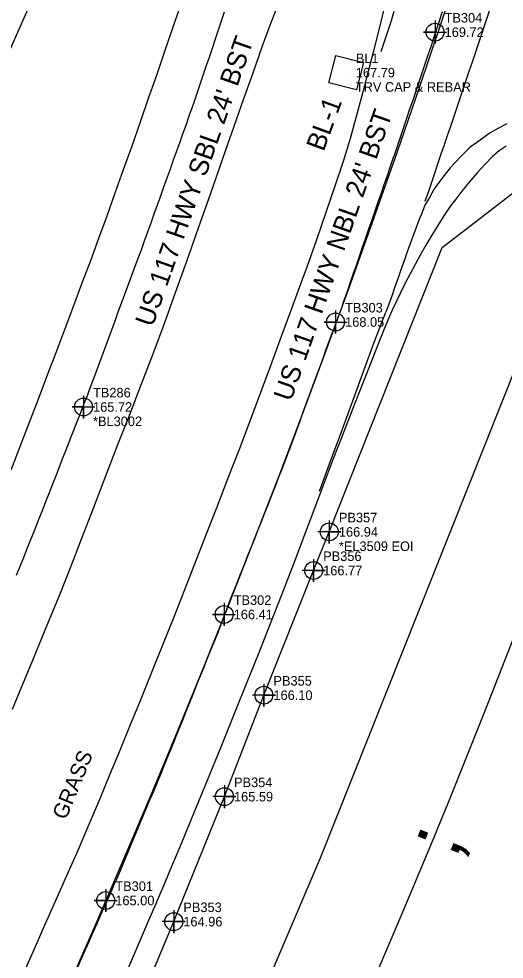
# Model space of a CAD drawing. Extents: x 2262665 to 2270527, y 505476 to 514960.
# Drawn here: x 2266059.9 to 2266186.8, y 509202.7 to 509448.8 of the extents above; entities that cross this region are included whole.
import ezdxf

# ---------------------------------------------------------------- set-up
doc = ezdxf.new("R2010")
doc.units = 0
for name, color, linetype in [('CTL Secondary Horizontal and Vertical CELL', 7, 'Continuous'), ('CTL Secondary Horizontal and Vertical Cogo Comment', 7, 'Continuous'), ('CTL Secondary Horizontal and Vertical Cogo Elevation', 7, 'Continuous'), ('CTL Secondary Horizontal and Vertical Cogo Number', 7, 'Continuous'), ('CTL Secondary Horizontal and Vertical Text', 7, 'Continuous'), ('Exist Horizontal Alignment', 7, 'Continuous'), ('Exist Other Culture Fence Line', 7, 'Continuous'), ('Exist Right of Way Control of Access CA Symbol CELL', 7, 'Continuous'), ('Exist Right of Way Control of Access Line', 7, 'Continuous'), ('Exist Roads EOP', 7, 'Continuous'), ('Exist Roads EOP Text', 7, 'Continuous'), ('Exist Roads EOT', 7, 'Continuous'), ('Exist Roads EOT Cogo Comment', 7, 'Continuous'), ('Exist Roads EOT Cogo Elevation', 7, 'Continuous'), ('Exist Roads EOT Cogo Number', 7, 'Continuous'), ('Exist Roads EOT Cogo Point CELL', 7, 'Continuous'), ('Exist Utilities Telephone UG Cable SUE LOS C', 7, 'Continuous'), ('Exist Utilities Telephone UG Cable SUE LOS C Cogo Comment', 7, 'Continuous'), ('Exist Utilities Telephone UG Cable SUE LOS C Cogo Elevation', 7, 'Continuous'), ('Exist Utilities Telephone UG Cable SUE LOS C Cogo Number', 7, 'Continuous'), ('Exist Utilities Telephone UG Cable SUE LOS C Cogo Point CELL', 7, 'Continuous'), ('Exist Utilities Water UG Line SUE LOS C', 7, 'Continuous'), ('Exist Vegetation Hedge Row Text', 7, 'Continuous')]:
    doc.layers.add(name, color=color, linetype=linetype)

msp = doc.modelspace()

# ---------------------------------------------------------------- linework, layer by layer
at = {"layer": 'CTL Secondary Horizontal and Vertical CELL'}
msp.add_line((2266145.46, 509434.72), (2266145.46, 509434.72), dxfattribs=at)
msp.add_lwpolyline([(2266140.98, 509432.05), (2266142.78, 509439.24), (2266149.99, 509437.44), (2266148.18, 509430.25)], close=True, dxfattribs=at)
at = {"layer": 'Exist Horizontal Alignment'}
msp.add_arc((2263436.25, 510359.19), 2882, 309.60499, 355.6461, dxfattribs=at)
at = {"layer": 'Exist Other Culture Fence Line'}
msp.add_lwpolyline([(2265935.11, 509632.71), (2265963.38, 509609.48), (2265980.51, 509595.58), (2265997.14, 509582.86), (2266019.57, 509564.09), (2266044.87, 509543.13), (2266056.13, 509534.43), (2266088.53, 509508.87), (2266073.89, 509477.67), (2266057.87, 509441.48), (2266042.86, 509409.08), (2266015.5, 509349.02), (2265987.41, 509287.57), (2265963.64, 509234.96), (2265936.09, 509175.26), (2265921.16, 509143.13)], dxfattribs=at)
at = {"layer": 'Exist Right of Way Control of Access CA Symbol CELL'}
msp.add_line((2266170.05, 509238.58), (2266170.05, 509238.58), dxfattribs=at)
at = {"layer": 'Exist Right of Way Control of Access Line'}
for radius, end in [(2754.56, 355.6461), (2954.56, 339.73535)]:
    msp.add_arc((2263436.25, 510359.19), radius, 309.60499, end, dxfattribs=at)
at = {"layer": 'Exist Roads EOP'}
for points in [[(2266102.21, 509452.41), (2266100.02, 509446.08), (2266097.93, 509440.01), (2266095.86, 509434.02), (2266093.75, 509427.95), (2266091.61, 509421.79), (2266089.42, 509415.54), (2266087.22, 509409.31), (2266085.04, 509403.21), (2266082.89, 509397.22), (2266080.75, 509391.36), (2266078.61, 509385.53), (2266076.42, 509379.64), (2266074.19, 509373.69), (2266071.92, 509367.67), (2266069.29, 509360.71), (2266067.76, 509356.68), (2266064.43, 509347.92), (2266061.31, 509339.79), (2266057.79, 509330.7)], [(2266127.29, 509451.55), (2266125.64, 509447.36), (2266123.55, 509441.66), (2266121.07, 509434.61), (2266118.59, 509427.6), (2266116.12, 509420.65), (2266113.25, 509412.49), (2266109.99, 509403.14), (2266106.79, 509394.01), (2266103.72, 509385.31), (2266100.79, 509377.1), (2266097.96, 509369.27), (2266095, 509361.32), (2266091.89, 509353.2), (2266088.81, 509345.2), (2266085.74, 509337.3), (2266082.58, 509329.13), (2266079.36, 509320.71), (2266076.3, 509312.78), (2266073.42, 509305.35), (2266070.41, 509297.84), (2266067.14, 509289.87), (2266065.19, 509285.15), (2266063.01, 509279.85), (2266060.59, 509273.97), (2266058.17, 509268.08)], [(2266060.79, 509198.24), (2266063.65, 509204.67), (2266066.56, 509211.27), (2266069.51, 509217.94), (2266072.48, 509224.59), (2266075.43, 509231.29), (2266078.33, 509238.09), (2266081.14, 509244.79), (2266083.81, 509251.19), (2266086.39, 509257.45), (2266088.96, 509263.71), (2266091.68, 509270.39), (2266094.71, 509277.88), (2266097.75, 509285.44), (2266100.49, 509292.3), (2266103.15, 509299.03), (2266105.95, 509306.19), (2266108.83, 509313.62), (2266111.75, 509321.14), (2266114.67, 509328.69), (2266117.56, 509336.22), (2266120.37, 509343.63), (2266123.05, 509350.83), (2266125.75, 509358.12), (2266128.59, 509365.74), (2266131.41, 509373.31), (2266134.02, 509380.45), (2266135.28, 509383.93), (2266137.79, 509391.04), (2266140.27, 509398.26), (2266142.61, 509405.13), (2266144.78, 509411.61), (2266146.71, 509417.9), (2266148.4, 509423.99), (2266149.93, 509429.7), (2266151.34, 509435.1), (2266152.81, 509440.8), (2266154.3, 509446.68), (2266155.43, 509451.4)], [(2266187.34, 509415.54), (2266185.52, 509414.28), (2266183.78, 509412.76), (2266181.82, 509410.79), (2266179.74, 509408.52), (2266177.67, 509406.07), (2266175.74, 509403.69), (2266174.12, 509401.64), (2266172.6, 509399.61), (2266171.03, 509397.27), (2266169.43, 509394.76), (2266167.85, 509392.17), (2266166.32, 509389.57), (2266164.87, 509387.01), (2266163.5, 509384.5), (2266162.18, 509382.05), (2266160.94, 509379.64), (2266159.77, 509377.29), (2266158.65, 509374.93), (2266157.54, 509372.54), (2266156.4, 509369.95), (2266155.19, 509367.03), (2266153.79, 509363.55), (2266152.09, 509359.27), (2266149.9, 509353.73), (2266147.05, 509346.45), (2266143.71, 509337.85), (2266141.94, 509333.21), (2266140.1, 509328.34), (2266138.26, 509323.49), (2266134.87, 509314.52), (2266131.79, 509306.39), (2266128.66, 509298.25), (2266125.46, 509290.07), (2266122.46, 509282.5), (2266119.62, 509275.41), (2266116.38, 509267.33), (2266112.71, 509258.25), (2266109.15, 509249.48), (2266105.7, 509241.06), (2266101.89, 509231.88), (2266099.81, 509226.94), (2266097.7, 509221.93), (2266095.62, 509217.02), (2266093.57, 509212.21), (2266091.56, 509207.5), (2266089.54, 509202.8), (2266087.46, 509198.03)]]:
    msp.add_lwpolyline(points, dxfattribs=at)
at = {"layer": 'Exist Roads EOT'}
for points in [[(2266059.31, 509303.25), (2266060.24, 509305.57), (2266061.18, 509307.89), (2266062.12, 509310.2), (2266063.06, 509312.52), (2266063.34, 509313.2), (2266064.25, 509315.53), (2266065.16, 509317.86), (2266066.07, 509320.19), (2266066.98, 509322.51), (2266067.89, 509324.84), (2266068.8, 509327.17), (2266069.72, 509329.5), (2266070.63, 509331.83), (2266071.54, 509334.15), (2266072.45, 509336.48), (2266073.36, 509338.81), (2266074.27, 509341.14), (2266075.18, 509343.46), (2266076.09, 509345.79), (2266077, 509348.12), (2266077.91, 509350.45), (2266078.13, 509351), (2266078.99, 509353.35), (2266079.86, 509355.69), (2266080.73, 509358.04), (2266081.59, 509360.38), (2266082.46, 509362.73), (2266083.32, 509365.07), (2266084.19, 509367.42), (2266085.06, 509369.76), (2266085.92, 509372.11), (2266086.79, 509374.45), (2266087.66, 509376.79), (2266088.52, 509379.14), (2266089.39, 509381.48), (2266090.26, 509383.83), (2266091.12, 509386.17), (2266091.95, 509388.41), (2266092.79, 509390.76), (2266093.64, 509393.11), (2266094.48, 509395.47), (2266095.32, 509397.82), (2266096.17, 509400.17), (2266097.01, 509402.53), (2266097.85, 509404.88), (2266098.7, 509407.23), (2266099.54, 509409.58), (2266100.38, 509411.94), (2266101.23, 509414.29), (2266102.07, 509416.64), (2266102.8, 509418.69), (2266103.63, 509421.04), (2266104.46, 509423.4), (2266105.29, 509425.76), (2266105.72, 509426.98), (2266106.52, 509429.35), (2266107.32, 509431.72), (2266108.12, 509434.09), (2266108.92, 509436.46), (2266109.72, 509438.82), (2266110.52, 509441.19), (2266111.32, 509443.56), (2266112.12, 509445.93), (2266112.92, 509448.3), (2266113.72, 509450.66)], [(2266170.58, 509450.62), (2266169.8, 509448.24), (2266169.03, 509445.87), (2266168.25, 509443.49), (2266167.67, 509441.72), (2266166.87, 509439.36), (2266166.07, 509436.99), (2266165.27, 509434.62), (2266164.47, 509432.25), (2266163.67, 509429.88), (2266162.88, 509427.52), (2266162.08, 509425.15), (2266161.28, 509422.78), (2266160.48, 509420.41), (2266159.68, 509418.04), (2266158.88, 509415.67), (2266158.08, 509413.31), (2266157.72, 509412.24), (2266156.9, 509409.88), (2266156.09, 509407.52), (2266155.28, 509405.15), (2266154.6, 509403.2), (2266153.79, 509400.84), (2266152.97, 509398.48), (2266152.16, 509396.11), (2266151.34, 509393.75), (2266150.53, 509391.39), (2266149.71, 509389.02), (2266148.9, 509386.66), (2266148.08, 509384.3), (2266147.27, 509381.94), (2266146.45, 509379.57), (2266145.64, 509377.21), (2266144.82, 509374.85), (2266144.33, 509373.41), (2266143.46, 509371.07), (2266142.59, 509368.72), (2266141.72, 509366.38), (2266140.98, 509364.4), (2266140.12, 509362.05), (2266139.26, 509359.7), (2266138.4, 509357.35), (2266137.54, 509355.01), (2266136.68, 509352.66), (2266135.83, 509350.31), (2266134.97, 509347.96), (2266134.11, 509345.62), (2266133.25, 509343.27), (2266132.39, 509340.92), (2266131.53, 509338.57), (2266130.68, 509336.23), (2266130.45, 509335.6), (2266129.55, 509333.27), (2266128.65, 509330.94), (2266127.75, 509328.61), (2266126.91, 509326.44), (2266125.99, 509324.12), (2266125.07, 509321.8), (2266124.15, 509319.47), (2266123.23, 509317.15), (2266122.31, 509314.83), (2266121.39, 509312.5), (2266120.47, 509310.18), (2266119.55, 509307.85), (2266118.63, 509305.53), (2266117.7, 509303.21), (2266116.78, 509300.88), (2266115.86, 509298.56), (2266115.36, 509297.3), (2266114.47, 509294.96), (2266113.59, 509292.63), (2266112.7, 509290.29), (2266111.98, 509288.4), (2266111.05, 509286.08), (2266110.12, 509283.76), (2266109.18, 509281.44), (2266108.25, 509279.13), (2266107.32, 509276.81), (2266106.39, 509274.49), (2266105.46, 509272.17), (2266104.53, 509269.85), (2266103.59, 509267.53), (2266102.66, 509265.21), (2266101.73, 509262.89), (2266100.8, 509260.57), (2266100.58, 509260.02), (2266099.64, 509257.71), (2266098.7, 509255.39), (2266097.76, 509253.07), (2266097.02, 509251.23), (2266096.05, 509248.93), (2266095.08, 509246.62), (2266094.11, 509244.32), (2266093.14, 509242.02), (2266092.17, 509239.71), (2266091.21, 509237.41), (2266090.24, 509235.1), (2266089.27, 509232.8), (2266088.3, 509230.49), (2266087.33, 509228.19), (2266086.36, 509225.88), (2266085.4, 509223.58), (2266084.87, 509222.32), (2266083.85, 509220.03), (2266082.84, 509217.75), (2266081.82, 509215.46), (2266081.3, 509214.27), (2266080.28, 509211.99), (2266079.27, 509209.7), (2266078.26, 509207.42), (2266077.25, 509205.13), (2266076.24, 509202.84), (2266075.23, 509200.56)], [(2266157.99, 509450.71), (2266157.21, 509448.33), (2266156.44, 509445.95), (2266155.66, 509443.58), (2266154.88, 509441.2), (2266154.55, 509440.18)], [(2266182.92, 509451.1), (2266182.15, 509448.73), (2266181.38, 509446.35), (2266180.79, 509444.56), (2266179.99, 509442.19), (2266179.2, 509439.82), (2266178.4, 509437.45), (2266177.6, 509435.08), (2266176.8, 509432.72), (2266176, 509430.35), (2266175.2, 509427.98), (2266174.41, 509425.61), (2266173.61, 509423.24), (2266172.81, 509420.87), (2266172.01, 509418.51), (2266171.21, 509416.14), (2266171.08, 509415.74), (2266170.27, 509413.37), (2266169.47, 509411.01), (2266168.66, 509408.64), (2266167.86, 509406.27), (2266167.06, 509403.91), (2266166.25, 509401.54), (2266166.08, 509401.04)], [(2266187.47, 509421.32), (2266185.32, 509420.24), (2266183.17, 509418.97), (2266182.51, 509418.59), (2266180.49, 509417.11), (2266179.89, 509416.67), (2266177.93, 509415.2), (2266176.13, 509413.46), (2266175.53, 509412.88), (2266173.81, 509411.06), (2266172.64, 509409.83), (2266171.11, 509407.85), (2266170.23, 509406.73), (2266168.78, 509404.7), (2266168.42, 509404.19), (2266167.26, 509402.1), (2266166.08, 509400.04), (2266165.16, 509397.72), (2266164.7, 509396.57), (2266163.82, 509394.23), (2266162.95, 509391.89), (2266162.08, 509389.54), (2266161.44, 509387.85), (2266160.62, 509385.49), (2266159.79, 509383.13), (2266158.97, 509380.77), (2266158.14, 509378.41), (2266157.47, 509376.5), (2266156.63, 509374.15), (2266155.88, 509372.05)], [(2266138.54, 509325.17), (2266141.43, 509333.07), (2266144.32, 509340.97), (2266147.21, 509348.87), (2266150.1, 509356.77), (2266152.99, 509364.68), (2266155.88, 509372.05)]]:
    msp.add_lwpolyline(points, dxfattribs=at)
at = {"layer": 'Exist Roads EOT Cogo Point CELL'}
for points in [[(2266168.72, 509448.35), (2266168.72, 509442.35), (2266168.72, 509445.35), (2266165.72, 509445.35), (2266171.72, 509445.35)], [(2266142.71, 509372.48), (2266142.71, 509366.48), (2266142.71, 509369.48), (2266139.71, 509369.48), (2266145.71, 509369.48)], [(2266076.81, 509350.24), (2266076.81, 509344.24), (2266076.81, 509347.24), (2266073.81, 509347.24), (2266079.81, 509347.24)], [(2266113.58, 509295.95), (2266113.58, 509289.95), (2266113.58, 509292.95), (2266110.58, 509292.95), (2266116.58, 509292.95)], [(2266082.63, 509221.08), (2266082.63, 509215.08), (2266082.63, 509218.08), (2266079.63, 509218.08), (2266085.63, 509218.08)]]:
    msp.add_lwpolyline(points, dxfattribs=at)
for centre in [(2266168.72, 509445.35), (2266142.71, 509369.48), (2266076.81, 509347.24), (2266113.58, 509292.95), (2266082.63, 509218.08)]:
    msp.add_circle(centre, 2.34, dxfattribs=at)
at = {"layer": 'Exist Utilities Telephone UG Cable SUE LOS C'}
for points in [[(2266141.08, 509314.55), (2266170.62, 509388.94), (2266199.91, 509411.54), (2266222.49, 509411.54), (2266235.12, 509401.86)], [(2266035.19, 509072.61), (2266044.1, 509090.49), (2266059.09, 509120.85), (2266073.19, 509151.71), (2266088.19, 509183.36), (2266100.41, 509212.55), (2266113.66, 509245.26), (2266123.97, 509271.82), (2266136.97, 509304.44), (2266141.08, 509314.55)]]:
    msp.add_lwpolyline(points, dxfattribs=at)
at = {"layer": 'Exist Utilities Telephone UG Cable SUE LOS C Cogo Point CELL'}
for points in [[(2266141.08, 509317.55), (2266141.08, 509311.55), (2266141.08, 509314.55), (2266144.08, 509314.55), (2266138.08, 509314.55)], [(2266136.97, 509307.44), (2266136.97, 509301.44), (2266136.97, 509304.44), (2266139.97, 509304.44), (2266133.97, 509304.44)], [(2266123.97, 509274.82), (2266123.97, 509268.82), (2266123.97, 509271.82), (2266126.97, 509271.82), (2266120.97, 509271.82)], [(2266113.66, 509248.26), (2266113.66, 509242.26), (2266113.66, 509245.26), (2266116.66, 509245.26), (2266110.66, 509245.26)], [(2266100.41, 509215.55), (2266100.41, 509209.55), (2266100.41, 509212.55), (2266103.41, 509212.55), (2266097.41, 509212.55)]]:
    msp.add_lwpolyline(points, dxfattribs=at)
for centre in [(2266141.08, 509314.55), (2266136.97, 509304.44), (2266123.97, 509271.82), (2266113.66, 509245.26), (2266100.41, 509212.55)]:
    msp.add_circle(centre, 2.34, dxfattribs=at)
at = {"layer": 'Exist Utilities Water UG Line SUE LOS C'}
msp.add_lwpolyline([(2266060.68, 509059.94), (2266102.63, 509144.29), (2266138.79, 509229.27), (2266207.31, 509401.38), (2266214.94, 509401.38), (2266230.6, 509388.77)], dxfattribs=at)

# ---------------------------------------------------------------- texts
at = {"layer": 'CTL Secondary Horizontal and Vertical Cogo Comment'}
msp.add_text('TRV CAP & REBAR', height=2.5, dxfattribs=at).set_placement((2266148.01, 509429.75))
at = {"layer": 'CTL Secondary Horizontal and Vertical Cogo Elevation'}
msp.add_text('167.79', height=2.5, dxfattribs=at).set_placement((2266148.01, 509433.5))
at = {"layer": 'CTL Secondary Horizontal and Vertical Cogo Number'}
msp.add_text('BL1', height=2.5, dxfattribs=at).set_placement((2266148.01, 509437.25))
at = {"layer": 'CTL Secondary Horizontal and Vertical Text'}
msp.add_text('BL-1', height=5, rotation=69.7863, dxfattribs=at).set_placement((2266139.59, 509413.91))
at = {"layer": 'Exist Right of Way Control of Access CA Symbol CELL'}
msp.add_text(';', height=15, rotation=67.7713, dxfattribs=at).set_placement((2266174.15, 509228.8))
at = {"layer": 'Exist Roads EOP Text'}
for s, p in [("US 117 HWY SBL 24' BST", (2266094.89, 509367.97)), ("US 117 HWY NBL 24' BST", (2266131.06, 509348.48))]:
    msp.add_text(s, height=5, rotation=70.6123, dxfattribs=at).set_placement(p)
at = {"layer": 'Exist Roads EOT Cogo Comment'}
msp.add_text('*BL3002', height=2.5, dxfattribs=at).set_placement((2266079.31, 509342.24))
at = {"layer": 'Exist Roads EOT Cogo Elevation'}
for s, p in [('169.72', (2266171.22, 509444.1)), ('168.05', (2266145.21, 509368.23)), ('165.72', (2266079.31, 509345.99)), ('166.41', (2266116.08, 509291.7)), ('165.00', (2266085.13, 509216.83))]:
    msp.add_text(s, height=2.5, dxfattribs=at).set_placement(p)
at = {"layer": 'Exist Roads EOT Cogo Number'}
for s, p in [('TB304', (2266171.22, 509447.85)), ('TB303', (2266145.21, 509371.98)), ('TB286', (2266079.31, 509349.74)), ('TB302', (2266116.08, 509295.45)), ('TB301', (2266085.13, 509220.58))]:
    msp.add_text(s, height=2.5, dxfattribs=at).set_placement(p)
at = {"layer": 'Exist Utilities Telephone UG Cable SUE LOS C Cogo Comment'}
msp.add_text('*EL3509 EOI', height=2.5, dxfattribs=at).set_placement((2266143.58, 509309.55))
at = {"layer": 'Exist Utilities Telephone UG Cable SUE LOS C Cogo Elevation'}
for s, p in [('166.94', (2266143.58, 509313.3)), ('166.77', (2266139.47, 509303.19)), ('166.10', (2266126.47, 509270.57)), ('165.59', (2266116.16, 509244.01)), ('164.96', (2266102.91, 509211.3))]:
    msp.add_text(s, height=2.5, dxfattribs=at).set_placement(p)
at = {"layer": 'Exist Utilities Telephone UG Cable SUE LOS C Cogo Number'}
for s, p in [('PB357', (2266143.58, 509317.05)), ('PB356', (2266139.47, 509306.94)), ('PB355', (2266126.47, 509274.32)), ('PB354', (2266116.16, 509247.76)), ('PB353', (2266102.91, 509215.05))]:
    msp.add_text(s, height=2.5, dxfattribs=at).set_placement(p)
at = {"layer": 'Exist Vegetation Hedge Row Text'}
msp.add_text('GRASS', height=4, rotation=67.5503, dxfattribs=at).set_placement((2266072.2, 509238.99))

doc.saveas('drawing.dxf')
